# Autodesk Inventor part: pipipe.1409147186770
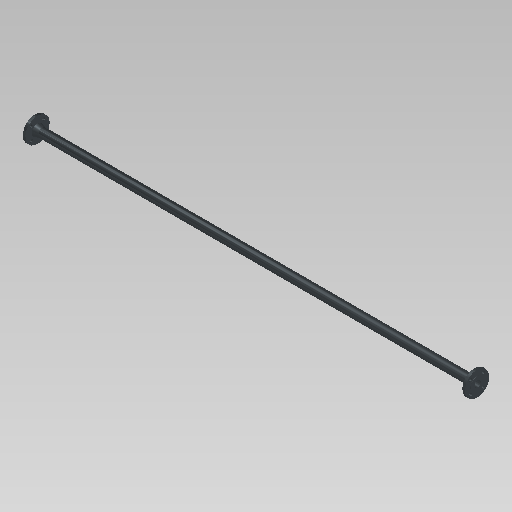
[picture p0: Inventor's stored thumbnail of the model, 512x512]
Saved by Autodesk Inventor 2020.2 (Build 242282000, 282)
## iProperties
Manager: www.cadconsulting.pl
Company: Fabian Stasiak CAD Consulting
IsCustomPart: 1
NAME: PIPING: ISO 2531 Pipe with Integrally Cast Flanges
DATA: <meta><inlinegroups number="1" deflen="50"></inlinegroups><connections number="2"></connections><angles><a>3.14159265358979</a></angles></meta>
Created: 2014-08
Material: Żeliwo sferoidalne
Description: Rury, łączniki, akcesoria z żeliwa sferoidalnego i ich złącza do zastosowań w instalacjach wodnych lub gazowych - Rura odlewana wraz z kołnierzami
Document SubType Name: Modeling
Standard: ISO 2531
Designer: F.Stasiak
Standard Revision: Fifth edition 1998-08-15
Standards Organization: ISO
Language: pl-PL
Size Designation: DN40 PN 10 - 500
Categories: <MemberInstance><Categories><Category DisplayName="Rury cienko- i grubościenne" InternalName="4347fa0f-2144-441d-94cd-e3e15c92b736" Mnemonic="TUBEANDPIPE"><Cate
Stock Number: ISO 2531 Rura odlewana wraz z kołnierzami DN40 PN 10
Density: 7.15 g/cm^3
Appearance: Ciemnoszary
Catalog Web Link: www.expertbooks.pl
L: 2720,000 mm
PL: 2720,000 mm
Author: F.Stasiak
Subject: Zbiór ćwiczeń. Autodesk Inventor 2020. Kurs Professional
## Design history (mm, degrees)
sketch "Sketch1"
  geometry: L1 (0, 0)-(-1360, 0); L2 (-1360, 0)-(-1360, 20); L3 (-2671.144, 27)-(-48.856, 27); L4 (-48.856, 27)-(-19, 35); L5 (-19, 35)-(-19, 75); L6 (-19, 75)-(-3, 75); L7 (-3, 75)-(-3, 42); L8 (-3, 42)-(0, 42); L9 (0, 42)-(0, 20); L10 (-2720, 20)-(0, 20); L11 (0, 20)-(0, 0); L12 (-2671.144, 27)-(-2701, 35); L13 (-2701, 35)-(-2701, 75); L14 (-2701, 75)-(-2717, 75); L15 (-2717, 75)-(-2717, 42); L16 (-2717, 42)-(-2720, 42); L17 (-2720, 42)-(-2720, 20); L18 (-2720, 20)-(-2720, 0); 2 further points
  constraints: 36 end point, 9 symmetric about line, 4 parallel, 2 coincident, 2 horizontal, 2 perpendicular, 1 collinear, 1 midpoint, 1 vertical, 7 other
  dimensions: "d0" = 7 distance between parallel lines of L10 L3 (= e); "d2" = 84 diameter of L8 L1 (= d1); "d3" = 3 distance of L7.end L8.end (= f1); "d4" = 19 distance between parallel lines of L9 L5 (= C7); "d5" = 150 diameter of L6 L1 (= D); "d6" = 70 diameter of L4.end L1 (= N3); "d7" = 15 deg angle of L3 L4; "d14" = 2720 distance between parallel lines of L9 L17 (= L); "d15" = 40 diameter of L10 L1 (= ID)
revolve "Revolution1" sketch "Sketch1" stored, may be unused: angle "d10" = 90 deg
sketch "Sketch2"
  geometry: L1 (-55, 0)-(0, 0); L2 (0, 0)-(-38.891, 38.891); C1 r 75 at (0, 0) reference; C2 r 42 at (0, 0) reference; C3 r 9.5 at (-38.891, 38.891); A1 r 55 centre (0, 0) between (-55, 0) and (-38.891, 38.891)
  constraints: 4 end point, 2 centre point, 2 point on circle, 1 coincident, 1 concentric, 1 horizontal
  dimensions: "d8" = 110 diameter of A1 (= K1); "d17" = 19 diameter of C3 (= L2); "d18" = 45 deg angle of L1 L2 (computed from NU)
extrude "Extrusion1" cut sketch "Sketch2" extent not by distance; taper "d9" = 0 deg; stored distance "d13" = 10
pattern_circular "Circular Pattern1" dims angle "d12" = 360 deg
workaxis "Work Axis1"
workpoint "Work Point1"
workaxis "Work Axis2"
workpoint "Work Point2"
body "Solid1"
other parameters: "e" = 7 [user parameter; used in 2 equation terms], "N3" = 70 [user parameter; used in 2 equation terms], "C7" = 19 [user parameter; used in 2 equation terms], "f1" = 3 [user parameter; used in 1 equation term], "d1" = 84 [user parameter; used in 1 equation term], "D" = 150 [user parameter; used in 1 equation term], "K1" = 110 [user parameter; used in 1 equation term], "L2" = 19 [user parameter; used in 1 equation term], "L" = 2720 (= PL) [user parameter; used in 1 equation term], "ID" = 40 [user parameter; used in 2 equation terms], "OD" = 54 [user parameter], "PL" = 2720 [user parameter; used in 1 equation term], "Size_Designation" = 12.345 [user parameter], "PLmin" = 107.21281 (= -7.4641 x e - 3.73205 x ID + 3.73205 x N3 + 2.5 x C7) [user parameter]
